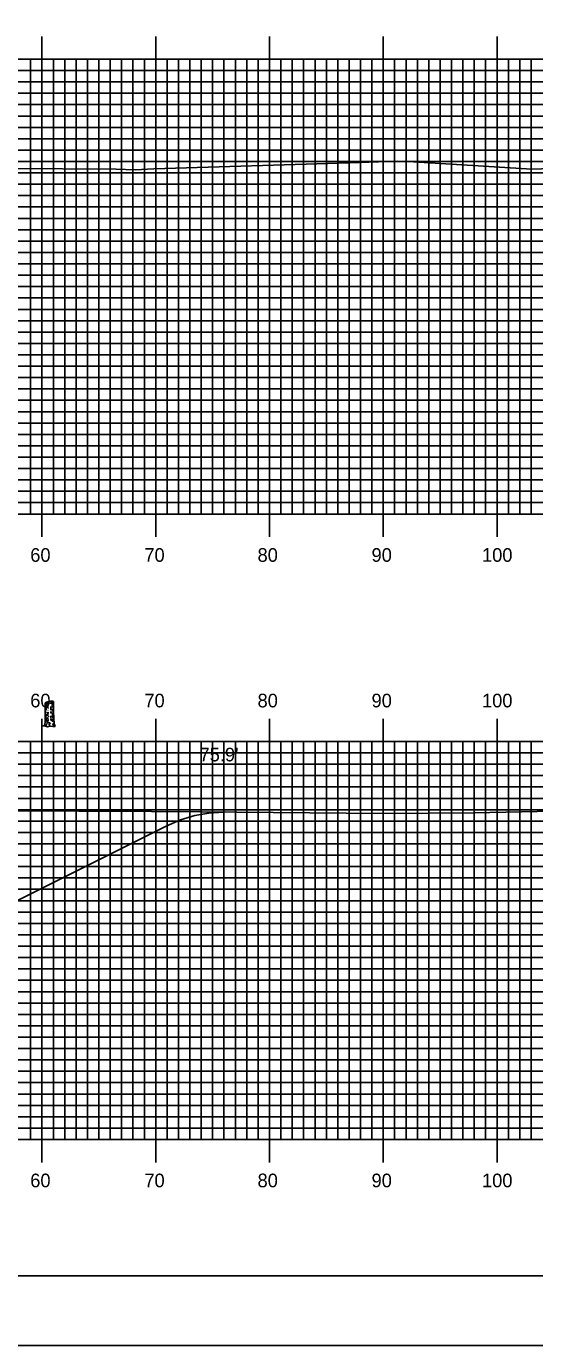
# Model space of a CAD drawing. Extents: x 1800355 to 1800699, y 442591 to 442811.
# Drawn here: x 1800579.7 to 1800624.3, y 442590.5 to 442706.6 of the extents above; entities that cross this region are included whole.
import ezdxf

# ---------------------------------------------------------------- set-up
doc = ezdxf.new("R2010")
doc.units = 0
for name, color, linetype in [('BORDER', 7, 'Continuous'), ('D_Roadway_Centerline', 7, 'Continuous'), ('D_Roadway_SlopeLines', 7, 'Continuous'), ('D_Text_Standard', 7, 'Continuous'), ('H_V ANNOTATION', 7, 'Continuous'), ('MAJOR', 7, 'Continuous'), ('MINOR', 7, 'Continuous'), ('PLOT BOUNDARY', 7, 'Continuous'), ('S_Roadway_Centerline', 7, 'Continuous'), ('S_Trees_Conifer_NonPay', 7, 'Continuous')]:
    doc.layers.add(name, color=color, linetype=linetype)

msp = doc.modelspace()

# ---------------------------------------------------------------- linework, layer by layer
at = {"layer": 'BORDER'}
msp.add_lwpolyline([(1800371.44, 442596.67), (1800691.44, 442596.67), (1800691.44, 442806.67), (1800371.44, 442806.67)], close=True, dxfattribs=at)
at = {"layer": 'D_Roadway_Centerline'}
msp.add_lwpolyline([(1800446.79, 442637.11), (1800448.04, 442637.03), (1800449.29, 442636.8), (1800450.54, 442636.41), (1800451.79, 442635.86), (1800486.86, 442618.33), (1800490.86, 442619.33), (1800501.04, 442621.87), (1800509.04, 442622.19), (1800521.04, 442621.95), (1800533.04, 442621.71), (1800541.04, 442621.39), (1800551.21, 442618.85), (1800555.21, 442617.85), (1800591.97, 442636.22), (1800593.22, 442636.77), (1800594.47, 442637.16), (1800595.72, 442637.38), (1800596.97, 442637.45)], dxfattribs=at)
at = {"layer": 'D_Roadway_SlopeLines'}
msp.add_lwpolyline([(1800555.21, 442617.85), (1800591.97, 442636.22), (1800593.22, 442636.77), (1800594.47, 442637.16), (1800595.72, 442637.38), (1800596.97, 442637.45)], dxfattribs=at)
at = {"layer": 'MAJOR'}
for p, q in [((1800581.04, 442705.67), (1800581.04, 442703.67)), ((1800591.04, 442705.67), (1800591.04, 442703.67)), ((1800601.04, 442705.67), (1800601.04, 442703.67)), ((1800611.04, 442705.67), (1800611.04, 442703.67)), ((1800621.04, 442705.67), (1800621.04, 442703.67)), ((1800381.04, 442703.67), (1800661.04, 442703.67)), ((1800381.04, 442703.67), (1800661.04, 442703.67)), ((1800581.04, 442663.67), (1800581.04, 442703.67)), ((1800591.04, 442663.67), (1800591.04, 442703.67)), ((1800601.04, 442663.67), (1800601.04, 442703.67)), ((1800611.04, 442663.67), (1800611.04, 442703.67)), ((1800621.04, 442663.67), (1800621.04, 442703.67)), ((1800381.04, 442698.67), (1800661.04, 442698.67)), ((1800381.04, 442693.67), (1800661.04, 442693.67)), ((1800381.04, 442688.67), (1800661.04, 442688.67)), ((1800381.04, 442683.67), (1800661.04, 442683.67)), ((1800381.04, 442678.67), (1800661.04, 442678.67)), ((1800381.04, 442673.67), (1800661.04, 442673.67)), ((1800381.04, 442668.67), (1800661.04, 442668.67)), ((1800381.04, 442663.67), (1800661.04, 442663.67)), ((1800381.04, 442663.67), (1800661.04, 442663.67)), ((1800581.04, 442661.66), (1800581.04, 442663.67)), ((1800591.04, 442661.66), (1800591.04, 442663.67)), ((1800601.04, 442661.66), (1800601.04, 442663.67)), ((1800611.04, 442661.66), (1800611.04, 442663.67)), ((1800621.04, 442661.66), (1800621.04, 442663.67)), ((1800581.04, 442645.67), (1800581.04, 442643.67)), ((1800591.04, 442645.67), (1800591.04, 442643.67)), ((1800601.04, 442645.67), (1800601.04, 442643.67)), ((1800611.04, 442645.67), (1800611.04, 442643.67)), ((1800621.04, 442645.67), (1800621.04, 442643.67)), ((1800381.04, 442643.67), (1800661.04, 442643.67)), ((1800381.04, 442643.67), (1800661.04, 442643.67)), ((1800581.04, 442608.67), (1800581.04, 442643.67)), ((1800591.04, 442608.67), (1800591.04, 442643.67)), ((1800601.04, 442608.67), (1800601.04, 442643.67)), ((1800611.04, 442608.67), (1800611.04, 442643.67)), ((1800621.04, 442608.67), (1800621.04, 442643.67)), ((1800381.04, 442638.67), (1800661.04, 442638.67)), ((1800381.04, 442633.67), (1800661.04, 442633.67)), ((1800381.04, 442628.67), (1800661.04, 442628.67)), ((1800381.04, 442623.67), (1800661.04, 442623.67)), ((1800381.04, 442618.67), (1800661.04, 442618.67)), ((1800381.04, 442613.67), (1800661.04, 442613.67)), ((1800381.04, 442608.67), (1800661.04, 442608.67)), ((1800381.04, 442608.67), (1800661.04, 442608.67)), ((1800581.04, 442606.66), (1800581.04, 442608.67)), ((1800591.04, 442606.66), (1800591.04, 442608.67)), ((1800601.04, 442606.66), (1800601.04, 442608.67)), ((1800611.04, 442606.66), (1800611.04, 442608.67)), ((1800621.04, 442606.66), (1800621.04, 442608.67))]:
    msp.add_line(p, q, dxfattribs=at)
at = {"layer": 'MINOR'}
for p, q in [((1800580.04, 442663.67), (1800580.04, 442703.67)), ((1800582.04, 442663.67), (1800582.04, 442703.67)), ((1800583.04, 442663.67), (1800583.04, 442703.67)), ((1800584.04, 442663.67), (1800584.04, 442703.67)), ((1800585.04, 442663.67), (1800585.04, 442703.67)), ((1800586.04, 442663.67), (1800586.04, 442703.67)), ((1800587.04, 442663.67), (1800587.04, 442703.67)), ((1800588.04, 442663.67), (1800588.04, 442703.67)), ((1800589.04, 442663.67), (1800589.04, 442703.67)), ((1800590.04, 442663.67), (1800590.04, 442703.67)), ((1800592.04, 442663.67), (1800592.04, 442703.67)), ((1800593.04, 442663.67), (1800593.04, 442703.67)), ((1800594.04, 442663.67), (1800594.04, 442703.67)), ((1800595.04, 442663.67), (1800595.04, 442703.67)), ((1800596.04, 442663.67), (1800596.04, 442703.67)), ((1800597.04, 442663.67), (1800597.04, 442703.67)), ((1800598.04, 442663.67), (1800598.04, 442703.67)), ((1800599.04, 442663.67), (1800599.04, 442703.67)), ((1800600.04, 442663.67), (1800600.04, 442703.67)), ((1800602.04, 442663.67), (1800602.04, 442703.67)), ((1800603.04, 442663.67), (1800603.04, 442703.67)), ((1800604.04, 442663.67), (1800604.04, 442703.67)), ((1800605.04, 442663.67), (1800605.04, 442703.67)), ((1800606.04, 442663.67), (1800606.04, 442703.67)), ((1800607.04, 442663.67), (1800607.04, 442703.67)), ((1800608.04, 442663.67), (1800608.04, 442703.67)), ((1800609.04, 442663.67), (1800609.04, 442703.67)), ((1800610.04, 442663.67), (1800610.04, 442703.67)), ((1800612.04, 442663.67), (1800612.04, 442703.67)), ((1800613.04, 442663.67), (1800613.04, 442703.67)), ((1800614.04, 442663.67), (1800614.04, 442703.67)), ((1800615.04, 442663.67), (1800615.04, 442703.67)), ((1800616.04, 442663.67), (1800616.04, 442703.67)), ((1800617.04, 442663.67), (1800617.04, 442703.67)), ((1800618.04, 442663.67), (1800618.04, 442703.67)), ((1800619.04, 442663.67), (1800619.04, 442703.67)), ((1800620.04, 442663.67), (1800620.04, 442703.67)), ((1800622.04, 442663.67), (1800622.04, 442703.67)), ((1800623.04, 442663.67), (1800623.04, 442703.67)), ((1800624.04, 442663.67), (1800624.04, 442703.67)), ((1800381.04, 442702.67), (1800661.04, 442702.67)), ((1800381.04, 442701.67), (1800661.04, 442701.67)), ((1800381.04, 442700.67), (1800661.04, 442700.67)), ((1800381.04, 442699.67), (1800661.04, 442699.67)), ((1800381.04, 442697.67), (1800661.04, 442697.67)), ((1800381.04, 442696.67), (1800661.04, 442696.67)), ((1800381.04, 442695.67), (1800661.04, 442695.67)), ((1800381.04, 442694.67), (1800661.04, 442694.67)), ((1800381.04, 442692.67), (1800661.04, 442692.67)), ((1800381.04, 442691.67), (1800661.04, 442691.67)), ((1800381.04, 442690.67), (1800661.04, 442690.67)), ((1800381.04, 442689.67), (1800661.04, 442689.67)), ((1800381.04, 442687.67), (1800661.04, 442687.67)), ((1800381.04, 442686.67), (1800661.04, 442686.67)), ((1800381.04, 442685.67), (1800661.04, 442685.67)), ((1800381.04, 442684.67), (1800661.04, 442684.67)), ((1800381.04, 442682.67), (1800661.04, 442682.67)), ((1800381.04, 442681.67), (1800661.04, 442681.67)), ((1800381.04, 442680.67), (1800661.04, 442680.67)), ((1800381.04, 442679.67), (1800661.04, 442679.67)), ((1800381.04, 442677.67), (1800661.04, 442677.67)), ((1800381.04, 442676.67), (1800661.04, 442676.67)), ((1800381.04, 442675.67), (1800661.04, 442675.67)), ((1800381.04, 442674.67), (1800661.04, 442674.67)), ((1800381.04, 442672.67), (1800661.04, 442672.67)), ((1800381.04, 442671.67), (1800661.04, 442671.67)), ((1800381.04, 442670.67), (1800661.04, 442670.67)), ((1800381.04, 442669.67), (1800661.04, 442669.67)), ((1800381.04, 442667.67), (1800661.04, 442667.67)), ((1800381.04, 442666.67), (1800661.04, 442666.67)), ((1800381.04, 442665.67), (1800661.04, 442665.67)), ((1800381.04, 442664.67), (1800661.04, 442664.67)), ((1800381.04, 442642.67), (1800661.04, 442642.67)), ((1800580.04, 442608.67), (1800580.04, 442643.67)), ((1800582.04, 442608.67), (1800582.04, 442643.67)), ((1800583.04, 442608.67), (1800583.04, 442643.67)), ((1800584.04, 442608.67), (1800584.04, 442643.67)), ((1800585.04, 442608.67), (1800585.04, 442643.67)), ((1800586.04, 442608.67), (1800586.04, 442643.67)), ((1800587.04, 442608.67), (1800587.04, 442643.67)), ((1800588.04, 442608.67), (1800588.04, 442643.67)), ((1800589.04, 442608.67), (1800589.04, 442643.67)), ((1800590.04, 442608.67), (1800590.04, 442643.67)), ((1800592.04, 442608.67), (1800592.04, 442643.67)), ((1800593.04, 442608.67), (1800593.04, 442643.67)), ((1800594.04, 442608.67), (1800594.04, 442643.67)), ((1800595.04, 442608.67), (1800595.04, 442643.67)), ((1800596.04, 442608.67), (1800596.04, 442643.67)), ((1800597.04, 442608.67), (1800597.04, 442643.67)), ((1800598.04, 442608.67), (1800598.04, 442643.67)), ((1800599.04, 442608.67), (1800599.04, 442643.67)), ((1800600.04, 442608.67), (1800600.04, 442643.67)), ((1800602.04, 442608.67), (1800602.04, 442643.67)), ((1800603.04, 442608.67), (1800603.04, 442643.67)), ((1800604.04, 442608.67), (1800604.04, 442643.67)), ((1800605.04, 442608.67), (1800605.04, 442643.67)), ((1800606.04, 442608.67), (1800606.04, 442643.67)), ((1800607.04, 442608.67), (1800607.04, 442643.67)), ((1800608.04, 442608.67), (1800608.04, 442643.67)), ((1800609.04, 442608.67), (1800609.04, 442643.67)), ((1800610.04, 442608.67), (1800610.04, 442643.67)), ((1800612.04, 442608.67), (1800612.04, 442643.67)), ((1800613.04, 442608.67), (1800613.04, 442643.67)), ((1800614.04, 442608.67), (1800614.04, 442643.67)), ((1800615.04, 442608.67), (1800615.04, 442643.67)), ((1800616.04, 442608.67), (1800616.04, 442643.67)), ((1800617.04, 442608.67), (1800617.04, 442643.67)), ((1800618.04, 442608.67), (1800618.04, 442643.67)), ((1800619.04, 442608.67), (1800619.04, 442643.67)), ((1800620.04, 442608.67), (1800620.04, 442643.67)), ((1800622.04, 442608.67), (1800622.04, 442643.67)), ((1800623.04, 442608.67), (1800623.04, 442643.67)), ((1800624.04, 442608.67), (1800624.04, 442643.67)), ((1800381.04, 442641.67), (1800661.04, 442641.67)), ((1800381.04, 442640.67), (1800661.04, 442640.67)), ((1800381.04, 442639.67), (1800661.04, 442639.67)), ((1800381.04, 442637.67), (1800661.04, 442637.67)), ((1800381.04, 442636.67), (1800661.04, 442636.67)), ((1800381.04, 442635.67), (1800661.04, 442635.67)), ((1800381.04, 442634.67), (1800661.04, 442634.67)), ((1800381.04, 442632.67), (1800661.04, 442632.67)), ((1800381.04, 442631.67), (1800661.04, 442631.67)), ((1800381.04, 442630.67), (1800661.04, 442630.67)), ((1800381.04, 442629.67), (1800661.04, 442629.67)), ((1800381.04, 442627.67), (1800661.04, 442627.67)), ((1800381.04, 442626.67), (1800661.04, 442626.67)), ((1800381.04, 442625.67), (1800661.04, 442625.67)), ((1800381.04, 442624.67), (1800661.04, 442624.67)), ((1800381.04, 442622.67), (1800661.04, 442622.67)), ((1800381.04, 442621.67), (1800661.04, 442621.67)), ((1800381.04, 442620.67), (1800661.04, 442620.67)), ((1800381.04, 442619.67), (1800661.04, 442619.67)), ((1800381.04, 442617.67), (1800661.04, 442617.67)), ((1800381.04, 442616.67), (1800661.04, 442616.67)), ((1800381.04, 442615.67), (1800661.04, 442615.67)), ((1800381.04, 442614.67), (1800661.04, 442614.67)), ((1800381.04, 442612.67), (1800661.04, 442612.67)), ((1800381.04, 442611.67), (1800661.04, 442611.67)), ((1800381.04, 442610.67), (1800661.04, 442610.67)), ((1800381.04, 442609.67), (1800661.04, 442609.67))]:
    msp.add_line(p, q, dxfattribs=at)
at = {"layer": 'PLOT BOUNDARY'}
msp.add_lwpolyline([(1800355.25, 442590.55), (1800695.25, 442590.55), (1800695.25, 442810.55), (1800355.25, 442810.55)], close=True, dxfattribs=at)
at = {"layer": 'S_Roadway_Centerline'}
for points in [[(1800568.72, 442694.12), (1800587.56, 442694.01), (1800589.22, 442693.94), (1800590.86, 442694.02), (1800608.06, 442694.55), (1800612.32, 442694.7), (1800613.24, 442694.68), (1800624.11, 442694), (1800634.35, 442694.35), (1800637.64, 442694.4), (1800647.4, 442694.33), (1800657.45, 442694.31), (1800659.1, 442694.32), (1800660.86, 442694.31), (1800661.04, 442694.31)], [(1800571.52, 442637.59), (1800590.67, 442637.52), (1800594.97, 442637.47), (1800610.98, 442637.33), (1800619.04, 442637.41), (1800634.29, 442637.71), (1800638.24, 442637.76), (1800642.34, 442637.72), (1800649.15, 442637.66), (1800657.16, 442637.72), (1800661.04, 442637.72)]]:
    msp.add_lwpolyline(points, dxfattribs=at)
at = {"layer": 'S_Trees_Conifer_NonPay'}
for p, q in [((1800581.41, 442647.01), (1800581.41, 442646.81)), ((1800581.41, 442646.74), (1800581.41, 442646.41)), ((1800581.41, 442646.29), (1800581.41, 442646.21)), ((1800581.41, 442646.1), (1800581.41, 442645.99)), ((1800581.57, 442646.89), (1800581.57, 442646.62)), ((1800581.57, 442646.26), (1800581.57, 442645.94)), ((1800581.83, 442647.07), (1800581.83, 442646.99)), ((1800581.83, 442646.74), (1800581.83, 442646.42)), ((1800581.83, 442646.32), (1800581.83, 442646.16)), ((1800581.96, 442646.78), (1800581.96, 442646.65)), ((1800581.96, 442646.54), (1800581.96, 442646.32)), ((1800581.96, 442646.22), (1800581.96, 442645.85)), ((1800581.39, 442645.91), (1800581.39, 442645.81)), ((1800581.41, 442645.7), (1800581.41, 442645.43)), ((1800581.57, 442645.77), (1800581.57, 442645.62)), ((1800581.57, 442645.56), (1800581.57, 442645.43)), ((1800581.61, 442645.9), (1800581.61, 442645.83)), ((1800581.83, 442645.93), (1800581.83, 442645.7)), ((1800581.83, 442645.64), (1800581.83, 442645.55)), ((1800581.95, 442645.65), (1800581.96, 442645.41)), ((1800582.02, 442645.43), (1800582.08, 442645.43))]:
    msp.add_line(p, q, dxfattribs=at)
for points in [[(1800581.33, 442647.05), (1800581.33, 442645.33), (1800581.26, 442645.07), (1800581.14, 442645.04), (1800581.36, 442645.02), (1800581.52, 442644.97), (1800581.73, 442645.02), (1800581.99, 442644.98), (1800582.2, 442644.98), (1800582.05, 442645.09), (1800581.97, 442645.24)], [(1800581.96, 442647.11), (1800581.96, 442647.01), (1800581.96, 442646.85)], [(1800582.07, 442645.07), (1800582.19, 442645.07), (1800582.1, 442645.2), (1800582.07, 442645.74), (1800582.05, 442646.26), (1800582.05, 442647.18)], [(1800581.36, 442645.02), (1800581.45, 442645.14), (1800581.47, 442645.25)], [(1800581.49, 442645.39), (1800581.48, 442645.34), (1800581.53, 442645.33), (1800581.53, 442645.39)], [(1800581.73, 442645.02), (1800581.68, 442645.2), (1800581.68, 442645.36)], [(1800581.68, 442645.25), (1800581.75, 442645.24), (1800581.77, 442645.3)]]:
    msp.add_lwpolyline(points, dxfattribs=at)
for centre, radius, start, end in [((1800581.36, 442647.05), 0.0263, 141.6195, 160.3798), ((1800581.35, 442647.05), 0.0186, 160.3798, 174.3267), ((1800581.35, 442647.05), 0.0141, 174.3267, 190.3798), ((1800581.35, 442647.05), 0.0141, 190.3798, 206.433), ((1800581.35, 442647.05), 0.0186, 206.433, 220.3798), ((1800581.35, 442646.93), 0.0143, 180, 196.0515), ((1800581.35, 442646.47), 0.0143, 180, 196.0515), ((1800581.35, 442646.47), 0.0189, 196.0515, 210), ((1800581.36, 442646.47), 0.0267, 210, 228.7494), ((1800581.35, 442646.26), 0.0143, 180, 196.0515), ((1800581.35, 442646.26), 0.0189, 196.0515, 210), ((1800581.36, 442646.26), 0.0267, 210, 228.7494), ((1800581.39, 442647.02), 0.0729, 130.3798, 141.6195), ((1800581.36, 442647.06), 0.0263, 220.3798, 239.1402), ((1800581.38, 442647.1), 0.0729, 239.1402, 250.3798), ((1800581.39, 442646.51), 0.0738, 228.7494, 240), ((1800581.39, 442646.3), 0.0738, 228.7494, 240), ((1800581.51, 442646.89), 0.245, 108.3946, 130.3798), ((1800581.47, 442646.66), 0.245, 240, 246.7914), ((1800581.47, 442646.44), 0.245, 240, 254.9514), ((1800581.44, 442647.26), 0.245, 250.3798, 272.3651), ((1800581.48, 442646.87), 0.245, 244.3148, 257.5375), ((1800581.47, 442647.12), 0.245, 254.8461, 261.8968), ((1800581.47, 442646.66), 0.245, 254.8461, 257.5454), ((1800582, 442645.39), 1.83, 100.3798, 108.3946), ((1800581.69, 442648.63), 1.77, 261.8968, 262.605), ((1800581.37, 442648.84), 1.83, 272.3651, 280.3798), ((1800581.69, 442648.63), 1.77, 264.3267, 266.0499), ((1800581.69, 442648.16), 1.77, 265.2285, 266.1325), ((1800581.69, 442648.38), 1.77, 265.8991, 267.5962), ((1800581.69, 442647.95), 1.77, 266.0429, 268.5525), ((1800582, 442645.39), 1.83, 92.3651, 100.3798), ((1800581.37, 442648.84), 1.83, 280.3798, 288.3946), ((1800581.69, 442648.38), 1.77, 272.7221, 274.4847), ((1800581.69, 442647.95), 1.77, 274.5361, 277.0026), ((1800581.69, 442648.63), 1.77, 276.2449, 278.1032), ((1800581.94, 442646.97), 0.245, 70.3798, 92.3651), ((1800581.9, 442647.12), 0.245, 278.1032, 284.1859), ((1800581.87, 442647.34), 0.245, 288.3946, 310.3798), ((1800581.9, 442646.66), 0.245, 284.1859, 300), ((1800581.9, 442647.12), 0.245, 291.7653, 300), ((1800581.9, 442646.44), 0.245, 292.1924, 300), ((1800582, 442647.13), 0.0729, 59.1402, 70.3798), ((1800582.02, 442647.17), 0.0263, 40.3798, 59.1402), ((1800581.98, 442647.21), 0.0729, 310.3798, 321.6195), ((1800581.99, 442646.97), 0.0738, 300, 311.2506), ((1800581.99, 442646.51), 0.0738, 300, 311.2506), ((1800581.99, 442646.3), 0.0738, 300, 311.2506), ((1800582.03, 442647.17), 0.0141, 10.3798, 26.433), ((1800582.03, 442647.17), 0.0186, 26.433, 40.3798), ((1800582.03, 442647.17), 0.0141, 354.3267, 10.3798), ((1800582.02, 442647.18), 0.0263, 321.6195, 340.3798), ((1800582.03, 442647.18), 0.0186, 340.3798, 354.3267), ((1800582.02, 442646.94), 0.0267, 311.2506, 330), ((1800582.03, 442646.93), 0.0189, 330, 343.9485), ((1800582.03, 442646.68), 0.0189, 330, 343.9485), ((1800582.02, 442646.69), 0.0267, 311.2506, 330), ((1800582.02, 442646.47), 0.0267, 311.2506, 330), ((1800582.03, 442646.47), 0.0189, 330, 343.9485), ((1800582.02, 442646.26), 0.0267, 311.2506, 330), ((1800582.03, 442646.26), 0.0189, 330, 343.9485), ((1800581.35, 442645.82), 0.0143, 180, 196.0515), ((1800581.35, 442645.61), 0.0143, 180, 196.0515), ((1800581.35, 442645.62), 0.0189, 196.0515, 210), ((1800581.36, 442645.62), 0.0267, 210, 228.7494), ((1800581.39, 442645.65), 0.0738, 228.7494, 240), ((1800581.47, 442645.8), 0.245, 240, 249.1675), ((1800581.47, 442646.23), 0.245, 254.9814, 261.8968), ((1800581.69, 442647.73), 1.77, 261.8968, 262.45), ((1800581.69, 442647.52), 1.77, 262.2622, 265.0496), ((1800581.69, 442647.31), 1.77, 266.0862, 268.2187), ((1800581.69, 442647.52), 1.77, 272.6293, 274.5612), ((1800581.69, 442647.31), 1.77, 274.2776, 276.3006), ((1800581.69, 442647.73), 1.77, 276.7966, 278.1032), ((1800581.69, 442647.52), 1.77, 277.63, 278.1032), ((1800581.9, 442646.23), 0.245, 278.1032, 284.3207), ((1800581.9, 442646.01), 0.245, 278.1032, 294.6056), ((1800581.9, 442645.8), 0.245, 284.0684, 300), ((1800581.99, 442645.65), 0.0738, 300, 302.05)]:
    msp.add_arc(centre, radius, start, end, dxfattribs=at)

# ---------------------------------------------------------------- texts
at = {"layer": 'D_Text_Standard'}
msp.add_text("75.9'", height=1.2, dxfattribs=at).set_placement((1800594.89, 442641.92))
at = {"layer": 'H_V ANNOTATION'}
for s, p in [('60', (1800580.01, 442659.47)), ('70', (1800590.04, 442659.47)), ('80', (1800599.99, 442659.47)), ('90', (1800610.01, 442659.47)), ('100', (1800619.72, 442659.47)), ('60', (1800580.01, 442646.67)), ('70', (1800590.04, 442646.67)), ('80', (1800599.99, 442646.67)), ('90', (1800610.01, 442646.67)), ('100', (1800619.72, 442646.67)), ('60', (1800580.01, 442604.47)), ('70', (1800590.04, 442604.47)), ('80', (1800599.99, 442604.47)), ('90', (1800610.01, 442604.47)), ('100', (1800619.72, 442604.47))]:
    msp.add_text(s, height=1.2, dxfattribs=at).set_placement(p)

doc.saveas('drawing.dxf')
